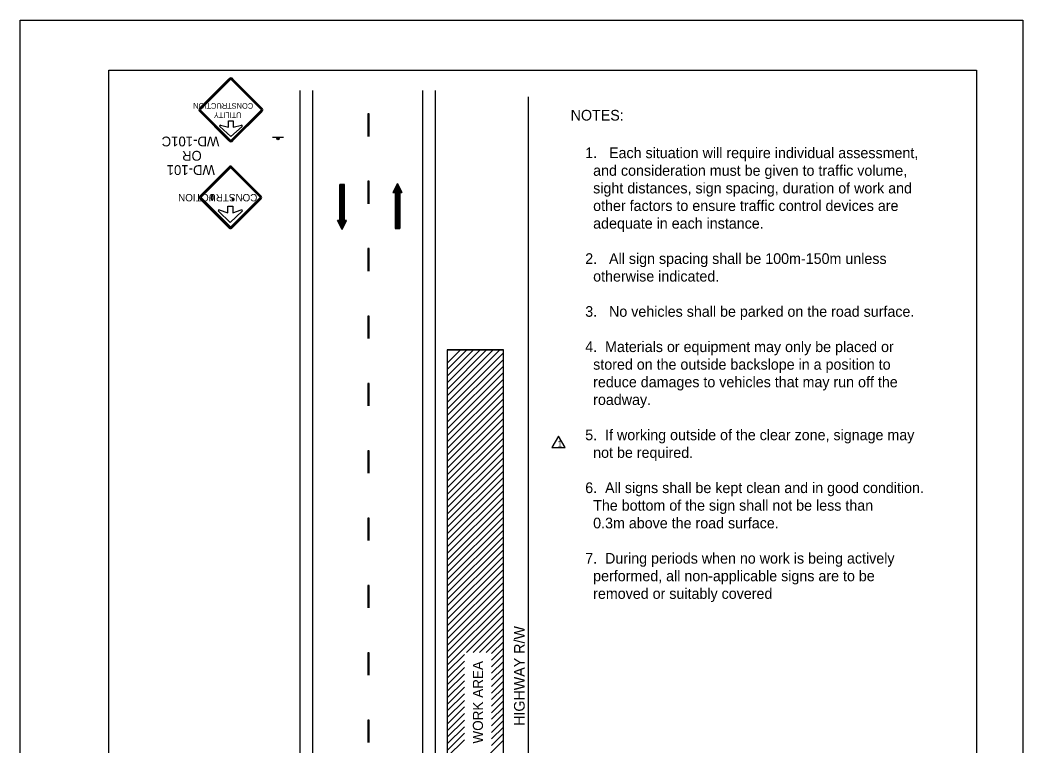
# Model space of a CAD drawing. Extents: x 1342 to 1558, y 178 to 457.
# Drawn here: x 1342.3 to 1558.3, y 300.5 to 456.9 of the extents above; entities that cross this region are included whole.
import ezdxf

# ---------------------------------------------------------------- set-up
doc = ezdxf.new("R2010")
doc.units = 0
for name, color, linetype in [('Level 1', 7, 'Continuous'), ('Level 10', 7, 'Continuous'), ('Level 2', 7, 'Continuous'), ('Level 44', 7, 'Continuous'), ('Level 60', 7, 'Continuous')]:
    doc.layers.add(name, color=color, linetype=linetype)

msp = doc.modelspace()

# ---------------------------------------------------------------- linework, layer by layer
at = {"layer": 'Level 1'}
for p, q in [((1394.78, 437.58), (1394.78, 437.58)), ((1389.95, 434.27), (1389.95, 434.27)), ((1389.95, 434.27), (1389.95, 434.27)), ((1389.95, 434.27), (1389.95, 434.27)), ((1381.02, 419.01), (1387.33, 425.32)), ((1381.14, 418.89), (1387.45, 425.2)), ((1381.27, 418.75), (1387.58, 425.06)), ((1387.65, 425.05), (1387.66, 425.06)), ((1387.66, 425.06), (1393.97, 418.75)), ((1387.8, 425.2), (1387.92, 425.32)), ((1387.8, 425.2), (1394.11, 418.89)), ((1387.8, 425.2), (1387.8, 425.2)), ((1387.92, 425.32), (1394.23, 419.01)), ((1387.92, 425.32), (1387.92, 425.32)), ((1387.33, 412.11), (1381.02, 418.42)), ((1387.45, 412.23), (1381.14, 418.54)), ((1387.58, 412.37), (1381.27, 418.68)), ((1393.97, 418.68), (1387.66, 412.37)), ((1394.11, 418.54), (1387.8, 412.23)), ((1394.23, 418.42), (1387.92, 412.11)), ((1388.06, 418.15), (1388.05, 418.15)), ((1388.06, 418.15), (1388.05, 418.15)), ((1387.57, 413.28), (1385.03, 415.76)), ((1385.19, 416.03), (1387.04, 415.39)), ((1387.04, 416.85), (1388.09, 416.85)), ((1387.04, 415.39), (1387.04, 416.85)), ((1390.11, 415.76), (1387.57, 413.28)), ((1388.09, 416.85), (1388.09, 415.39)), ((1388.09, 415.39), (1389.94, 416.03)), ((1387.33, 412.11), (1387.45, 412.23)), ((1387.45, 412.23), (1387.45, 412.23))]:
    msp.add_line(p, q, dxfattribs=at)
for points in [[(1380.97, 437.98), (1387.28, 444.29)], [(1381.09, 437.86), (1387.4, 444.17)], [(1381.21, 437.74), (1387.52, 444.05)], [(1387.84, 444.05), (1394.15, 437.74)], [(1387.95, 444.17), (1394.27, 437.86)], [(1388.07, 444.29), (1394.38, 437.97)], [(1387.28, 430.88), (1380.97, 437.19)], [(1387.4, 430.99), (1381.09, 437.31)], [(1387.52, 431.11), (1381.21, 437.42)], [(1394.15, 437.42), (1387.84, 431.11)], [(1394.27, 437.3), (1387.95, 430.99)], [(1394.38, 437.18), (1388.07, 430.87)], [(1385.45, 434.27), (1387.2, 433.82), (1387.2, 435.19), (1388.19, 435.19), (1388.19, 433.82), (1389.95, 434.27)], [(1385.45, 434.27), (1387.2, 433.82), (1387.2, 435.19), (1388.19, 435.19), (1388.19, 433.82), (1389.95, 434.27)], [(1385.45, 434.27), (1387.2, 433.82), (1387.2, 435.19), (1388.19, 435.19), (1388.19, 433.82), (1389.95, 434.27)], [(1390.09, 434.02), (1387.7, 431.84), (1385.31, 434.02)], [(1390.09, 434.02), (1387.7, 431.84), (1385.31, 434.02)], [(1390.09, 434.02), (1387.7, 431.84), (1385.31, 434.02)], [(1383.82, 419.1), (1383.81, 419.11), (1383.81, 419.12), (1383.8, 419.13), (1383.78, 419.14), (1383.78, 419.15), (1383.77, 419.16), (1383.76, 419.16), (1383.75, 419.18), (1383.74, 419.18), (1383.74, 419.19), (1383.73, 419.19), (1383.72, 419.19), (1383.71, 419.2), (1383.69, 419.2), (1383.68, 419.2), (1383.67, 419.2), (1383.66, 419.2), (1383.65, 419.2), (1383.64, 419.2), (1383.63, 419.2), (1383.62, 419.19), (1383.6, 419.19), (1383.59, 419.19), (1383.58, 419.18), (1383.57, 419.16), (1383.56, 419.15), (1383.55, 419.15), (1383.55, 419.14), (1383.54, 419.13), (1383.53, 419.12), (1383.51, 419.11), (1383.51, 419.1), (1383.5, 419.06), (1383.5, 419.03), (1383.49, 419), (1383.48, 418.96), (1383.48, 418.93), (1383.47, 418.89), (1383.47, 418.85), (1383.46, 418.82), (1383.46, 418.78), (1383.46, 418.75), (1383.46, 418.71), (1383.46, 418.68), (1383.46, 418.65), (1383.46, 418.61), (1383.46, 418.58), (1383.46, 418.55), (1383.47, 418.5), (1383.47, 418.47), (1383.47, 418.43), (1383.48, 418.4), (1383.48, 418.37), (1383.49, 418.33), (1383.5, 418.3), (1383.5, 418.26), (1383.51, 418.23), (1383.53, 418.22), (1383.53, 418.21), (1383.54, 418.2), (1383.55, 418.19), (1383.55, 418.17), (1383.56, 418.16), (1383.57, 418.16), (1383.58, 418.15), (1383.59, 418.14), (1383.6, 418.14), (1383.62, 418.14), (1383.63, 418.13), (1383.64, 418.13), (1383.65, 418.13), (1383.66, 418.13), (1383.67, 418.13), (1383.68, 418.13), (1383.69, 418.13), (1383.71, 418.13), (1383.72, 418.13), (1383.73, 418.14), (1383.74, 418.14), (1383.74, 418.15), (1383.75, 418.15), (1383.76, 418.16), (1383.77, 418.16), (1383.77, 418.17), (1383.78, 418.19), (1383.8, 418.19), (1383.8, 418.2), (1383.81, 418.21), (1383.81, 418.22), (1383.82, 418.23), (1383.82, 418.24), (1383.82, 418.25), (1383.82, 418.26), (1383.83, 418.3), (1383.84, 418.32), (1383.84, 418.35), (1383.85, 418.39), (1383.86, 418.42), (1383.86, 418.46), (1383.86, 418.49)], [(1383.82, 419.1), (1383.81, 419.11), (1383.81, 419.12), (1383.8, 419.13), (1383.78, 419.14), (1383.78, 419.15), (1383.77, 419.16), (1383.76, 419.16), (1383.75, 419.18), (1383.74, 419.18), (1383.74, 419.19), (1383.73, 419.19), (1383.72, 419.19), (1383.71, 419.2), (1383.69, 419.2), (1383.68, 419.2), (1383.67, 419.2), (1383.66, 419.2), (1383.65, 419.2), (1383.64, 419.2), (1383.63, 419.2), (1383.62, 419.19), (1383.6, 419.19), (1383.59, 419.19), (1383.58, 419.18), (1383.57, 419.16), (1383.56, 419.15), (1383.55, 419.15), (1383.55, 419.14), (1383.54, 419.13), (1383.53, 419.12), (1383.51, 419.11), (1383.51, 419.1), (1383.5, 419.06), (1383.5, 419.03), (1383.49, 419), (1383.48, 418.96), (1383.48, 418.93), (1383.47, 418.89), (1383.47, 418.85), (1383.46, 418.82), (1383.46, 418.78), (1383.46, 418.75), (1383.46, 418.71), (1383.46, 418.68), (1383.46, 418.65), (1383.46, 418.61), (1383.46, 418.58), (1383.46, 418.55), (1383.47, 418.5), (1383.47, 418.47), (1383.47, 418.43), (1383.48, 418.4), (1383.48, 418.37), (1383.49, 418.33), (1383.5, 418.3), (1383.5, 418.26), (1383.51, 418.23), (1383.53, 418.22), (1383.53, 418.21), (1383.54, 418.2), (1383.55, 418.19), (1383.55, 418.17), (1383.56, 418.16), (1383.57, 418.16), (1383.58, 418.15), (1383.59, 418.14), (1383.6, 418.14), (1383.62, 418.14), (1383.63, 418.13), (1383.64, 418.13), (1383.65, 418.13), (1383.66, 418.13), (1383.67, 418.13), (1383.68, 418.13), (1383.69, 418.13), (1383.71, 418.13), (1383.72, 418.13), (1383.73, 418.14), (1383.74, 418.14), (1383.74, 418.15), (1383.75, 418.15), (1383.76, 418.16), (1383.77, 418.16), (1383.77, 418.17), (1383.78, 418.19), (1383.8, 418.19), (1383.8, 418.2), (1383.81, 418.21), (1383.81, 418.22), (1383.82, 418.23), (1383.82, 418.24), (1383.82, 418.25), (1383.82, 418.26), (1383.83, 418.3), (1383.84, 418.32), (1383.84, 418.35), (1383.85, 418.39), (1383.86, 418.42), (1383.86, 418.46), (1383.86, 418.49)], [(1383.86, 418.49), (1383.87, 418.52), (1383.87, 418.56), (1383.87, 418.59), (1383.87, 418.62), (1383.87, 418.66), (1383.87, 418.69), (1383.87, 418.73), (1383.87, 418.76), (1383.87, 418.79), (1383.86, 418.83), (1383.86, 418.86), (1383.86, 418.89), (1383.85, 418.93), (1383.85, 418.96), (1383.84, 419), (1383.83, 419.03), (1383.83, 419.06), (1383.82, 419.1)], [(1383.86, 418.49), (1383.87, 418.52), (1383.87, 418.56), (1383.87, 418.59), (1383.87, 418.62), (1383.87, 418.66), (1383.87, 418.69), (1383.87, 418.73), (1383.87, 418.76), (1383.87, 418.79), (1383.86, 418.83), (1383.86, 418.86), (1383.86, 418.89), (1383.85, 418.93), (1383.85, 418.96), (1383.84, 419), (1383.83, 419.03), (1383.83, 419.06), (1383.82, 419.1)], [(1388.06, 418.51), (1388.05, 418.51), (1388.04, 418.5), (1388.03, 418.5), (1388.02, 418.5), (1388.01, 418.5), (1388.01, 418.49), (1388, 418.49), (1387.99, 418.49), (1387.97, 418.48), (1387.96, 418.47), (1387.95, 418.46), (1387.94, 418.44), (1387.94, 418.43), (1387.94, 418.42), (1387.93, 418.4), (1387.93, 418.39), (1387.93, 418.38), (1387.93, 418.35), (1387.92, 418.34), (1387.92, 418.33), (1387.92, 418.31), (1387.93, 418.3), (1387.93, 418.29), (1387.93, 418.26), (1387.93, 418.25), (1387.94, 418.24), (1387.94, 418.22), (1387.95, 418.21), (1387.95, 418.2), (1387.96, 418.19), (1387.97, 418.19), (1387.97, 418.17), (1387.99, 418.17), (1388, 418.16), (1388.01, 418.16), (1388.02, 418.16), (1388.03, 418.15), (1388.04, 418.15), (1388.05, 418.15), (1388.06, 418.15)], [(1388.06, 418.51), (1388.05, 418.51), (1388.04, 418.5), (1388.03, 418.5), (1388.02, 418.5), (1388.01, 418.5), (1388.01, 418.49), (1388, 418.49), (1387.99, 418.49), (1387.97, 418.48), (1387.96, 418.47), (1387.95, 418.46), (1387.94, 418.44), (1387.94, 418.43), (1387.94, 418.42), (1387.93, 418.4), (1387.93, 418.39), (1387.93, 418.38), (1387.93, 418.35), (1387.92, 418.34), (1387.92, 418.33), (1387.92, 418.31), (1387.93, 418.3), (1387.93, 418.29), (1387.93, 418.26), (1387.93, 418.25), (1387.94, 418.24), (1387.94, 418.22), (1387.95, 418.21), (1387.95, 418.2), (1387.96, 418.19), (1387.97, 418.19), (1387.97, 418.17), (1387.99, 418.17), (1388, 418.16), (1388.01, 418.16), (1388.02, 418.16), (1388.03, 418.15), (1388.04, 418.15), (1388.05, 418.15), (1388.06, 418.15)], [(1388.05, 418.15), (1388.3, 418.15), (1388.3, 418.51), (1388.05, 418.51)], [(1388.05, 418.15), (1388.3, 418.15), (1388.3, 418.51), (1388.05, 418.51)], [(1389.93, 418.51), (1390.09, 418.42)]]:
    msp.add_lwpolyline(points, dxfattribs=at)
msp.add_lwpolyline([(1458.24, 367.28), (1456.82, 364.81), (1459.66, 364.81)], close=True, dxfattribs=at)
for centre, radius, start, end in [((1387.68, 443.89), 0.558, 44.995, 134.9949), ((1387.68, 443.89), 0.39, 44.995, 134.9949), ((1387.68, 443.89), 0.223, 44.995, 134.9949), ((1381.37, 437.58), 0.558, 134.995, 224.995), ((1381.37, 437.58), 0.39, 134.995, 224.995), ((1381.37, 437.58), 0.223, 134.995, 224.995), ((1393.99, 437.58), 0.223, 314.995, 44.995), ((1393.99, 437.58), 0.39, 314.995, 44.995), ((1393.99, 437.58), 0.558, 314.995, 44.9949), ((1385.41, 434.13), 0.15, 75.5925, 227.6952), ((1385.41, 434.13), 0.15, 75.5925, 227.6952), ((1385.41, 434.13), 0.15, 75.5925, 227.6952), ((1389.99, 434.13), 0.15, 312.3048, 104.4075), ((1389.99, 434.13), 0.15, 312.3048, 104.4075), ((1389.99, 434.13), 0.15, 312.3048, 104.4075), ((1387.68, 431.27), 0.558, 224.995, 314.995), ((1387.68, 431.27), 0.558, 224.995, 314.995), ((1387.68, 431.27), 0.39, 224.995, 314.995), ((1387.68, 431.27), 0.223, 224.995, 314.995), ((1387.62, 425.03), 0.413, 45, 135), ((1387.62, 425.03), 0.25, 44.9995, 135.0003), ((1387.62, 425.03), 0.0553, 45, 135.0007), ((1381.31, 418.71), 0.413, 135, 225), ((1381.31, 418.71), 0.25, 135, 225), ((1381.31, 418.71), 0.0552, 135, 224.9983), ((1393.93, 418.71), 0.0552, 315, 45), ((1393.93, 418.71), 0.25, 315, 45.0007), ((1393.93, 418.71), 0.413, 315, 45), ((1385.14, 415.87), 0.162, 70.9366, 225.756), ((1390, 415.87), 0.162, 314.244, 109.0634), ((1387.62, 412.4), 0.413, 225.0001, 315), ((1387.62, 412.4), 0.25, 225.0001, 315), ((1387.62, 412.4), 0.0552, 225, 315)]:
    msp.add_arc(centre, radius, start, end, dxfattribs=at)
at = {"layer": 'Level 10'}
for p, q in [((1402.52, 441.71), (1402.52, 425.37)), ((1405.24, 441.71), (1405.24, 425.37)), ((1428.95, 441.71), (1428.95, 425.37)), ((1431.69, 441.71), (1431.69, 425.37)), ((1451.69, 440.38), (1451.69, 195.81)), ((1402.52, 437.4), (1402.52, 437.4)), ((1402.52, 425.37), (1402.52, 373)), ((1405.24, 425.37), (1405.24, 373)), ((1428.95, 425.37), (1428.95, 373)), ((1431.69, 425.37), (1431.69, 373)), ((1411.17, 413.74), (1411.17, 421.48)), ((1412.14, 421.48), (1411.17, 421.48)), ((1411.17, 412.77), (1411.17, 421.48)), ((1411.29, 412.53), (1411.29, 421.48)), ((1411.41, 412.29), (1411.41, 421.48)), ((1411.53, 412.05), (1411.53, 421.48)), ((1411.65, 411.8), (1411.65, 421.48)), ((1411.77, 412.05), (1411.77, 421.48)), ((1411.89, 412.29), (1411.89, 421.48)), ((1412.02, 412.53), (1412.02, 421.48)), ((1412.14, 413.74), (1412.14, 421.48)), ((1412.14, 412.77), (1412.14, 421.48)), ((1423.57, 421.7), (1422.6, 419.76)), ((1423.33, 421.21), (1423.33, 412.02)), ((1423.45, 421.45), (1423.45, 412.02)), ((1423.57, 421.7), (1423.57, 412.02)), ((1423.57, 421.7), (1424.54, 419.76)), ((1423.69, 421.45), (1423.69, 412.02)), ((1423.81, 421.21), (1423.81, 412.02)), ((1422.6, 419.76), (1423.09, 419.76)), ((1422.73, 420), (1422.73, 419.76)), ((1422.85, 420.25), (1422.85, 419.76)), ((1422.97, 420.49), (1422.97, 419.76)), ((1423.09, 420.73), (1423.09, 412.02)), ((1423.09, 419.76), (1423.09, 412.02)), ((1423.21, 420.97), (1423.21, 412.02)), ((1423.93, 420.97), (1423.93, 412.02)), ((1424.06, 420.73), (1424.06, 412.02)), ((1424.06, 419.76), (1424.06, 412.02)), ((1424.06, 419.76), (1424.54, 419.76)), ((1424.18, 420.49), (1424.18, 419.76)), ((1424.3, 420.25), (1424.3, 419.76)), ((1424.42, 420), (1424.42, 419.76)), ((1411.65, 411.8), (1410.68, 413.74)), ((1411.17, 413.74), (1410.68, 413.74)), ((1410.81, 413.5), (1410.81, 413.74)), ((1410.93, 413.25), (1410.93, 413.74)), ((1411.05, 413.01), (1411.05, 413.74)), ((1411.65, 411.8), (1412.62, 413.74)), ((1412.62, 413.74), (1412.14, 413.74)), ((1412.26, 413.01), (1412.26, 413.74)), ((1412.38, 413.25), (1412.38, 413.74)), ((1412.5, 413.5), (1412.5, 413.74)), ((1423.09, 412.02), (1424.06, 412.02)), ((1434.29, 383.01), (1437.12, 385.84)), ((1434.29, 381.6), (1438.53, 385.84)), ((1434.29, 380.18), (1439.94, 385.84)), ((1434.29, 378.77), (1441.36, 385.84)), ((1434.29, 377.35), (1442.77, 385.84)), ((1434.29, 375.94), (1444.19, 385.84)), ((1434.29, 374.53), (1445.6, 385.84)), ((1434.29, 373.11), (1446.38, 385.21)), ((1434.29, 371.7), (1446.38, 383.79)), ((1434.29, 370.28), (1446.38, 382.38)), ((1434.29, 368.87), (1446.38, 380.96)), ((1434.29, 367.45), (1446.38, 379.55)), ((1434.29, 366.04), (1446.38, 378.13)), ((1434.29, 364.63), (1446.38, 376.72)), ((1434.29, 363.21), (1446.38, 375.31)), ((1434.29, 361.8), (1446.38, 373.89)), ((1402.52, 373), (1402.52, 195.81)), ((1405.24, 373), (1405.24, 195.81)), ((1428.95, 373), (1428.95, 195.81)), ((1431.69, 373), (1431.69, 195.81)), ((1434.29, 360.38), (1446.38, 372.48)), ((1434.29, 358.97), (1446.38, 371.06)), ((1434.29, 357.56), (1446.38, 369.65)), ((1434.29, 356.14), (1446.38, 368.24)), ((1434.29, 354.73), (1446.38, 366.82)), ((1434.29, 353.31), (1446.38, 365.41)), ((1434.29, 351.9), (1446.38, 363.99)), ((1434.29, 350.48), (1446.38, 362.58)), ((1434.29, 349.07), (1446.38, 361.16)), ((1434.29, 347.66), (1446.38, 359.75)), ((1434.29, 346.24), (1446.38, 358.34)), ((1434.29, 344.83), (1446.38, 356.92)), ((1434.29, 343.41), (1446.38, 355.51)), ((1434.29, 342), (1446.38, 354.09)), ((1434.29, 340.58), (1446.38, 352.68)), ((1434.29, 339.17), (1446.38, 351.26)), ((1434.29, 337.76), (1446.38, 349.85)), ((1434.29, 336.34), (1446.38, 348.44)), ((1434.29, 334.93), (1446.38, 347.02)), ((1434.29, 333.51), (1446.38, 345.61)), ((1434.29, 332.1), (1446.38, 344.19)), ((1434.29, 330.69), (1446.38, 342.78)), ((1434.29, 329.27), (1446.38, 341.37)), ((1434.29, 327.86), (1446.38, 339.95)), ((1434.29, 326.44), (1446.38, 338.54)), ((1434.29, 325.03), (1446.38, 337.12)), ((1434.29, 323.61), (1446.38, 335.71)), ((1434.29, 322.2), (1446.38, 334.29)), ((1434.29, 320.79), (1446.38, 332.88)), ((1434.29, 319.37), (1446.38, 331.47)), ((1434.29, 317.96), (1446.38, 330.05)), ((1438.44, 320.69), (1446.38, 328.64)), ((1439.85, 320.69), (1446.38, 327.22)), ((1441.27, 320.69), (1446.38, 325.81)), ((1442.68, 320.69), (1446.38, 324.39)), ((1443.82, 320.42), (1446.38, 322.98)), ((1434.29, 316.54), (1437.98, 320.24)), ((1443.82, 319), (1446.38, 321.57)), ((1443.82, 317.59), (1446.38, 320.15)), ((1434.29, 315.13), (1437.98, 318.82)), ((1443.82, 316.18), (1446.38, 318.74)), ((1434.29, 313.71), (1437.98, 317.41)), ((1434.29, 312.3), (1437.98, 316)), ((1443.82, 314.76), (1446.38, 317.32)), ((1443.82, 313.35), (1446.38, 315.91)), ((1434.29, 310.89), (1437.98, 314.58)), ((1443.82, 311.93), (1446.38, 314.5)), ((1434.29, 309.47), (1437.98, 313.17)), ((1434.29, 308.06), (1437.98, 311.75)), ((1443.82, 310.52), (1446.38, 313.08)), ((1443.82, 309.1), (1446.38, 311.67)), ((1434.29, 306.64), (1437.98, 310.34)), ((1434.29, 305.23), (1437.98, 308.93)), ((1443.82, 307.69), (1446.38, 310.25)), ((1434.29, 303.81), (1437.98, 307.51)), ((1443.82, 306.28), (1446.38, 308.84)), ((1443.82, 304.86), (1446.38, 307.42)), ((1434.29, 302.4), (1437.98, 306.1)), ((1434.29, 300.99), (1437.98, 304.68)), ((1443.82, 303.45), (1446.38, 306.01)), ((1443.82, 302.03), (1446.38, 304.6)), ((1434.29, 299.57), (1437.98, 303.27)), ((1443.82, 300.62), (1446.38, 303.18)), ((1434.29, 298.16), (1437.98, 301.86)), ((1434.29, 289.67), (1446.38, 301.77))]:
    msp.add_line(p, q, dxfattribs=at)
at = {"layer": 'Level 2'}
for p, q in [((1417.2, 436.7), (1417.2, 431.86)), ((1417.49, 436.7), (1417.2, 436.7)), ((1417.49, 431.86), (1417.49, 436.7)), ((1417.2, 422.19), (1417.2, 417.35)), ((1417.49, 422.19), (1417.2, 422.19)), ((1417.49, 417.35), (1417.49, 422.19)), ((1417.2, 407.67), (1417.2, 402.84)), ((1417.49, 407.67), (1417.2, 407.67)), ((1417.49, 402.84), (1417.49, 407.67)), ((1417.2, 393.16), (1417.2, 388.32)), ((1417.49, 393.16), (1417.2, 393.16)), ((1417.49, 388.32), (1417.49, 393.16)), ((1417.2, 378.65), (1417.2, 373.81)), ((1417.49, 378.65), (1417.2, 378.65)), ((1417.49, 373.81), (1417.49, 378.65)), ((1417.2, 364.13), (1417.2, 359.29)), ((1417.49, 364.13), (1417.2, 364.13)), ((1417.49, 359.29), (1417.49, 364.13)), ((1417.2, 349.62), (1417.2, 344.78)), ((1417.49, 349.62), (1417.2, 349.62)), ((1417.49, 344.78), (1417.49, 349.62)), ((1417.2, 335.1), (1417.2, 330.27)), ((1417.49, 335.1), (1417.2, 335.1)), ((1417.49, 330.27), (1417.49, 335.1)), ((1417.2, 320.59), (1417.2, 315.75)), ((1417.49, 320.59), (1417.2, 320.59)), ((1417.49, 315.75), (1417.49, 320.59)), ((1417.2, 306.08), (1417.2, 301.24)), ((1417.49, 306.08), (1417.2, 306.08)), ((1417.49, 301.24), (1417.49, 306.08))]:
    msp.add_line(p, q, dxfattribs=at)
at = {"layer": 'Level 44'}
msp.add_line((1399.05, 431.65), (1396.63, 431.65), dxfattribs=at)
for radius in [0.242, 0.121]:
    msp.add_circle((1397.83, 431.38), radius, dxfattribs=at)
at = {"layer": 'Level 60'}
for p, q in [((1342.28, 456.92), (1342.28, 456.92)), ((1434.29, 385.84), (1446.38, 385.84))]:
    msp.add_line(p, q, dxfattribs=at)
for points in [[(1342.28, 456.92), (1558.28, 456.92), (1558.28, 177.92), (1342.28, 177.92)], [(1361.41, 446.11), (1548.28, 446.11), (1548.28, 188.73), (1361.41, 188.73)], [(1446.38, 385.84), (1434.29, 385.84), (1434.29, 234.9), (1446.38, 234.9)]]:
    msp.add_lwpolyline(points, close=True, dxfattribs=at)

# ---------------------------------------------------------------- texts
at = {"layer": 'Level 1'}
for s, height, rotation, p in [('CONSTRUCTION', 1.2, 180, (1392.5, 439.02)), ('UTILITY', 1.2, 180, (1389.99, 437.04)), ('CONSTRUCTION', 1.584, 180, (1393.39, 419.45)), ('1', 1.45, 360, (1458.01, 364.87))]:
    msp.add_text(s, height=height, rotation=rotation, dxfattribs=at).set_placement(p)
at = {"layer": 'Level 10'}
for s, p in [('NOTES:', (1460.87, 435.27)), ('1.   Each situation will require individual assessment,', (1464.01, 427.17)), ('  and consideration must be given to traffic volume,', (1464.01, 423.37)), ('  sight distances, sign spacing, duration of work and', (1464.01, 419.57)), ('  other factors to ensure traffic control devices are', (1464.01, 415.78)), ('  adequate in each instance.', (1464.01, 411.98)), ('2.   All sign spacing shall be 100m-150m unless', (1464.01, 404.38)), ('  otherwise indicated.', (1464.01, 400.58)), ('3.   No vehicles shall be parked on the road surface.', (1464.01, 392.99)), ('4.  Materials or equipment may only be placed or', (1464.01, 385.39)), ('  stored on the outside backslope in a position to', (1464.01, 381.59)), ('  reduce damages to vehicles that may run off the', (1464.01, 377.8)), ('  roadway.', (1464.01, 374)), ('5.  If working outside of the clear zone, signage may ', (1464.01, 366.4)), ('  not be required.', (1464.01, 362.6)), ('6.  All signs shall be kept clean and in good condition.', (1464.01, 355.01)), ('  The bottom of the sign shall not be less than', (1464.01, 351.21)), ('  0.3m above the road surface.', (1464.01, 347.41)), ('7.  During periods when no work is being actively', (1464.01, 339.81)), ('  performed, all non-applicable signs are to be', (1464.01, 336.02)), ('  removed or suitably covered', (1464.01, 332.22))]:
    msp.add_text(s, height=2.298, dxfattribs=at).set_placement(p)
for s, height, rotation, p in [('WD-101C', 2.115, 180, (1385.2, 431.82)), ('OR', 2.115, 180, (1381.41, 428.74)), ('WD-101', 2.115, 180, (1384.24, 425.66)), ('HIGHWAY R/W', 2.298, 90, (1450.97, 304.85)), ('WORK AREA', 2.177, 90, (1441.98, 301.04))]:
    msp.add_text(s, height=height, rotation=rotation, dxfattribs=at).set_placement(p)

doc.saveas('drawing.dxf')
